Omron CX-Programmer project 新工程 (CX-Programmer 4.01)

# PLC 新PLC1: CJ1M CPU22

## Program 新程序1 (cyclic task 0)

### Section 段1

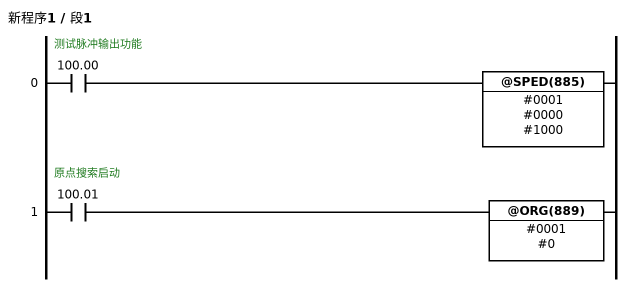
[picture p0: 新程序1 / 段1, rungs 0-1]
; rung 0: 测试脉冲输出功能
LD 100.00
@SPED(885) #0001 #0000 #1000
; rung 1: 原点搜索启动
LD 100.01
@ORG(889) #0001 #0

### Section END
; rung 0
END(001)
